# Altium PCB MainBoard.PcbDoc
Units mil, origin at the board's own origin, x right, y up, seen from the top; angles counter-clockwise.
Board outline 3600 x 2800 mil, 2 copper layers (Top Layer, Bottom Layer); 55 components, 52 nets, 242 pads, 74 vias.
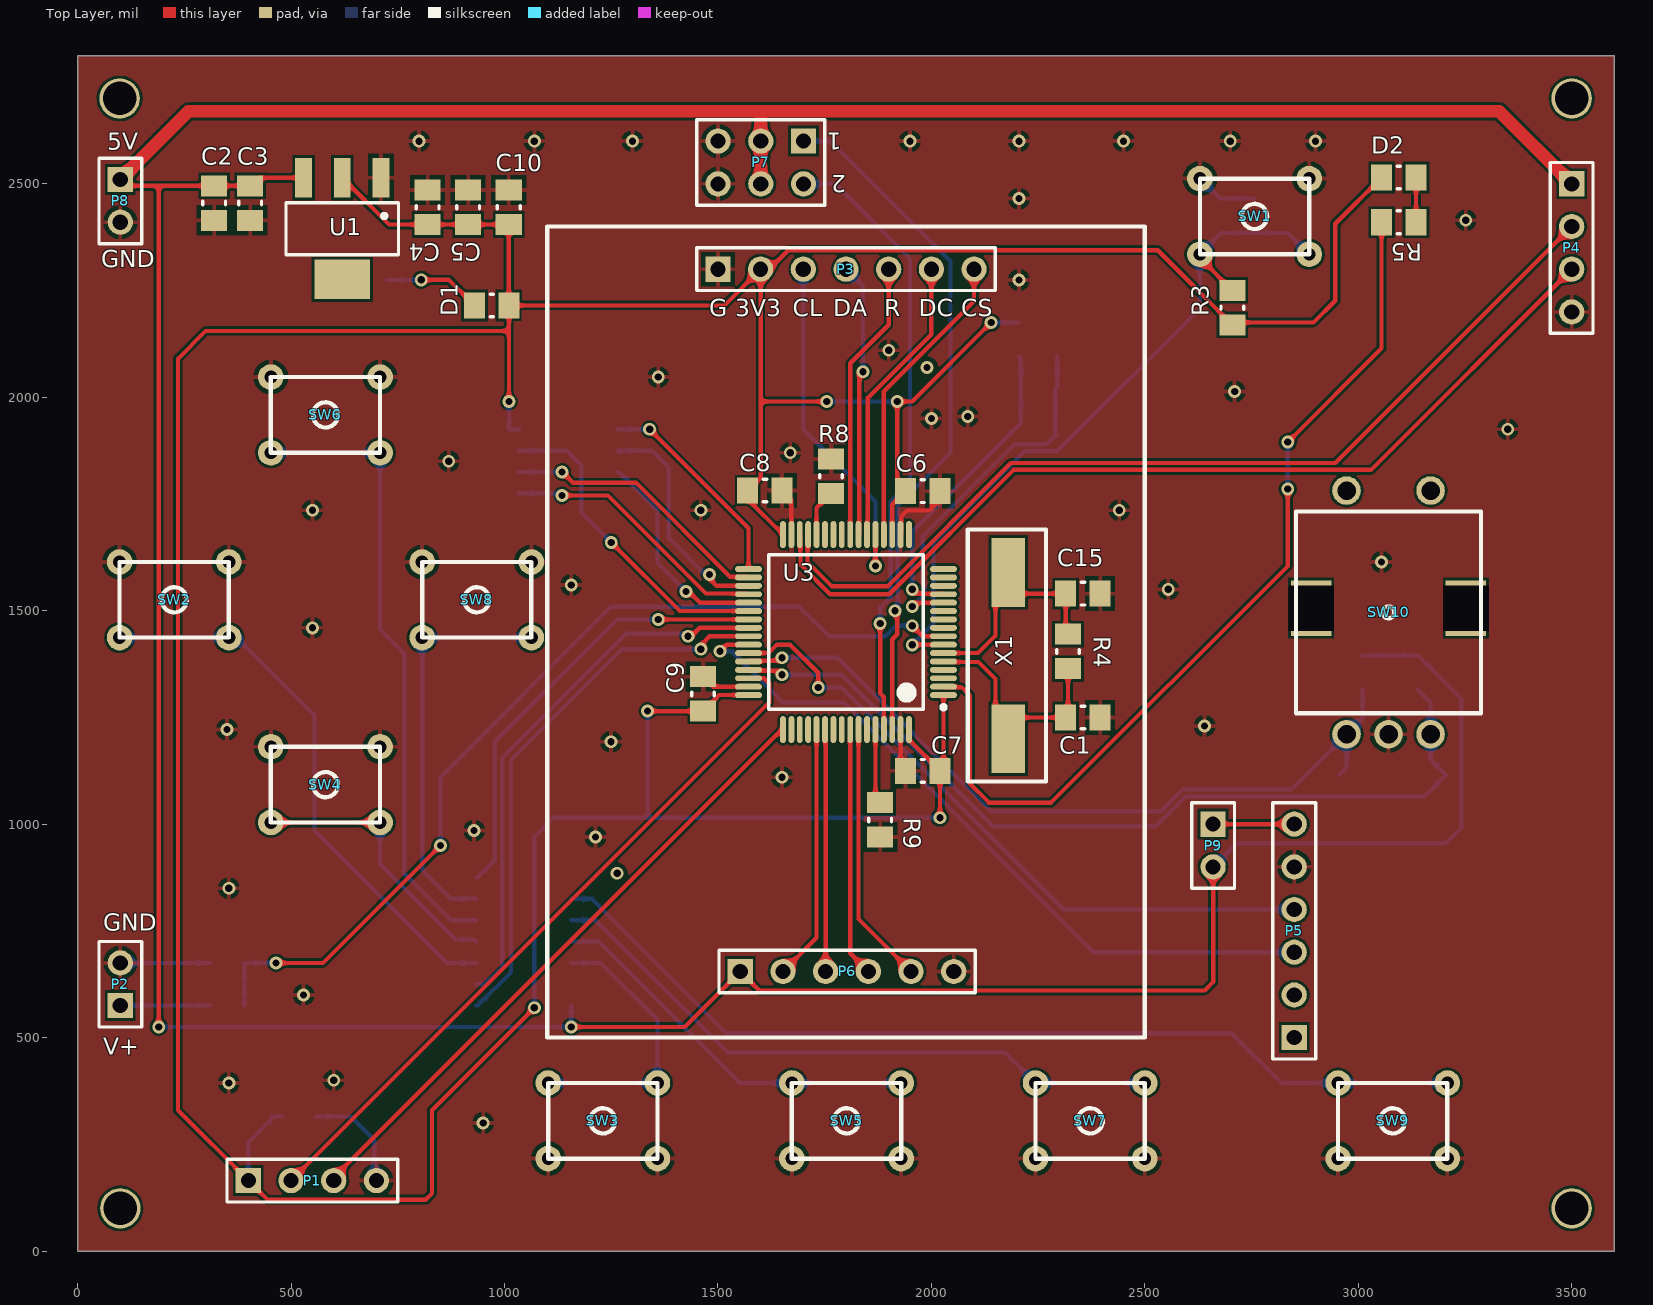
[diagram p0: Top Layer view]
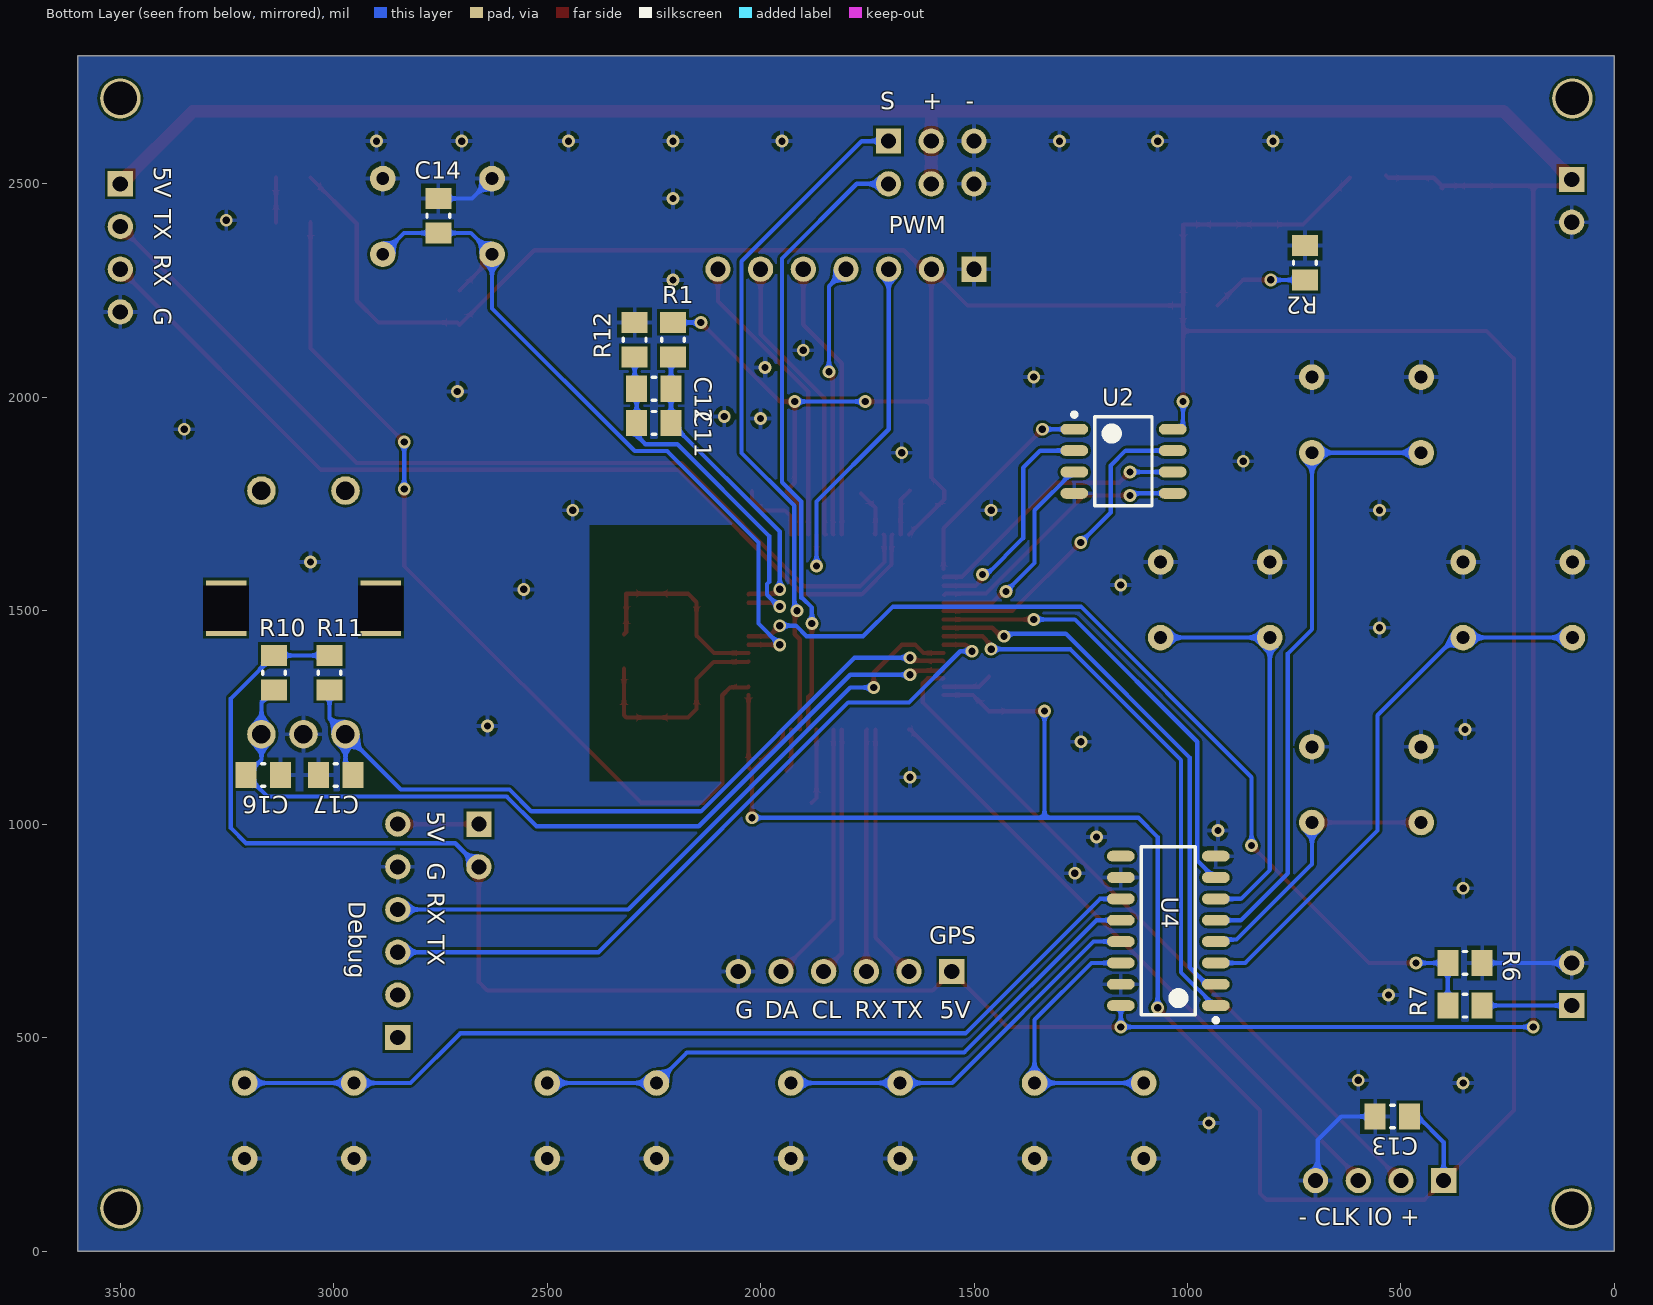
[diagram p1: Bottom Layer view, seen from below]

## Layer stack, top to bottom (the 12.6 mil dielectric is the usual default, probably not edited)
Top Solder: solder mask 0.4, Solder Resist, Dk 3.5
Top Layer: signal copper 1.4
Dielectric 1: dielectric 12.6, FR-4, Dk 4.8
Bottom Layer: signal copper 1.4
Bottom Solder: solder mask 0.4, Solder Resist, Dk 3.5

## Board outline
0,0 0,2800 3600,2800 3600,0

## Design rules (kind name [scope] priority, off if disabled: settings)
Clearance [All] p1: gap=6 ignorepadtopadclearanceinfootprint=TRUE except(0: Arc-Hole Track-Hole SMDPad-Hole THPad-Hole Via-Hole Fill-Hole Poly-Hole Region-Hole Text-Hole; 10: Arc-THPad Arc-Via Arc-Text Track-THPad Track-Via Track-Text SMDPad-THPad SMDPad-Via SMDPad-Text THPad-THPad THPad-Via THPad-Text Via-Via Via-Text Fill-Text Poly-Text Region-Text Text-Text)
PolygonConnect [All] p1: connectstyle=Relief reliefconductorwidth=10 reliefentries=4 polygonreliefangle="90 Angle" airgapwidth=10
RoutingVias [All] p1: holewidth=17 width=30 viastyle="Through Hole" minholewidth=17 minwidth=30 maxholewidth=28 maxwidth=50
SolderMaskExpansion [All] p1: expansion=4
Width [All] p1: maxlimit=30 minlimit=10 preferedwidth=10 minimp=50.000000 maximp=50.000000 favimp=50.000000
30 further rules are at their usual default settings.

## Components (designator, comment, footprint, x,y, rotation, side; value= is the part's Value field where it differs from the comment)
C1 "22p" 0805 2355,1250 r0 top
C2 "106" 0805 320,2455 r90 top
C3 "104" 0805 404.33,2455 r90 top
C4 "104" 0805 820,2445 r270 top
C5 "106" 0805 915,2445 r270 top
C6 "104" 0805 1980,1780 r180 top
C7 "104" 0805 1980,1125 r0 top
C8 "104" 0805 1610,1781.5 r180 top
C9 "104" 0805 1465,1305 r270 top
C10 "104" 0805 1010,2445 r270 top
C11 "104" 0805 2250,1940 r180 bottom
C12 "106" 0805 2250,2020 r180 bottom
C13 "104" 0805 520,315 r180 bottom
C14 "105" 0805 2755,2425 r270 bottom
C15 "22p" 0805 2355,1540 r0 top
C16 "104" 0805 3165,1115 r0 bottom
C17 "104" 0805 2995,1115 r0 bottom
D1 "LED" 0805 970,2215 r180 top
D2 "LED" 0805 3095,2515 r0 top
P1 "SWD" HDR1X4 400,165 r0 top
P2 "BAT Power" HDR1X2 100,575 r90 top
P3 "OLED" HDR1X7 1500,2300 r0 top
P4 "Telem" HDR1X4 3500,2500 r270 top
P5 "Debug" HDR1X6 2850,500 r90 top
P6 "GPS" HDR1X6 1552.36,655 r0 top
P7 "PWM" HDR2X3 1700.35,2600 r180 top
P8 "GND" HDR1X2 100,2510 r270 top
P9 "Header 2" HDR1X2 2660,1000 r270 top
R1 "0R" 0805 2205.35,2135 r90 bottom
R2 "510" 0805 725,2315 r90 bottom
R3 "10k" 0805 2705,2210 r90 top
R4 "1M" 0805 2320,1404.65 r270 top
R5 "510" 0805 3095,2410 r180 top
R6 "5k1" 0805 350,575 r180 bottom
R7 "1k" 0805 350,675 r0 bottom
R8 "10k" 0805 1765,1815 r270 top
R9 "10k" 0805 1880,1010 r270 top
R10 "10k" 0805 3140,1355 r90 bottom
R11 "10k" 0805 3010,1355 r270 bottom
R12 "0R" 0805 2295,2135 r90 bottom
SW1 "" Btn 2885,2335 r180 top
SW2 "" Btn 98.43,1614.17 r0 top
SW3 "" Btn 1102.36,393.7 r0 top
SW4 "" Btn 452.76,1181.1 r0 top
SW5 "" Btn 1673.23,393.7 r0 top
SW6 "" Btn 452.76,2047.24 r0 top
SW7 "" Btn 2244.09,393.7 r0 top
SW8 "" Btn 807.09,1614.17 r0 top
SW9 "" Btn 2952.76,393.7 r0 top
SW10 "EC11" EC11 2972.44,1781.5 r0 top
U1 "AMS1117-3.3" SOT223 620,2395 r270 top
U2 "MB85RS16" SOP8 1150,1850 r180 bottom
U3 "STM32F103R" LQFP64 1800,1450 r180 top
U4 "74LS165" SOP16 1045,750 r0 bottom
X1 "8M" 49SMD 2180,1395 r270 top

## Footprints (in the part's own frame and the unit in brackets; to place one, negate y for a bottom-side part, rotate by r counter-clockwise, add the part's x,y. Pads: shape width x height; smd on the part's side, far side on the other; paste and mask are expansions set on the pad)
49SMD [mm] "Chip Capacitor, 2-Leads, Body 12.65x4.50mm, IPC High Density"
  rect 4.1x2 smd: 1(-4.95,0) 2(4.95,0)
  silkscreen extent -7.5,-2.4 7.5,2.25
0805 [mm]
  rect 1.25x1.55 smd: 1(-1.025,0) 2(1.025,0)
  silkscreen extent -0.1,-0.67 0.1,0.67
Btn [mil]
  round 60 hole 30: 1(0,0) 1(255.91,0) 2(0,-177.17) 2(255.91,-177.17)
  silkscreen extent 0,-177 256,0
EC11 [mm]
  round 1.7 hole 1.1: 1(5,0) 2(0,0) 3(0,-14.5) 4(2.5,-14.5) 5(5,-14.5)
  rect 2.4x3.3 hole 2.7 square: ""(-2.1,-7) ""(7.1,-7)
  silkscreen extent -3,-13.25 8,-1.25
HDR1X2 [mm] "Connector; Header; 2 Position"
  rect 1.5x1.5 hole 0.9: 1(0,0)
  round 1.5 hole 0.9: 2(2.54,0)
  silkscreen extent -1.27,-1.27 3.81,1.27
HDR1X4 [mm] "Connector; Header; 4 Position"
  rect 1.5x1.5 hole 0.9: 1(0,0)
  round 1.5 hole 0.9: 2(2.54,0) 3(5.08,0) 4(7.62,0)
  silkscreen extent -1.27,-1.27 8.89,1.27
HDR1X6 [mm] "Connector; Header; 6 Position"
  rect 1.5x1.5 hole 0.9: 1(0,0)
  round 1.5 hole 0.9: 2(2.54,0) 3(5.08,0) 4(7.62,0) 5(10.16,0) 6(12.7,0)
  silkscreen extent -1.27,-1.27 13.97,1.27
HDR1X7 [mm] "Connector; Header; 7 Position"
  rect 1.5x1.5 hole 0.9: 1(0,0)
  round 1.5 hole 0.9: 2(2.54,0) 3(5.08,0) 4(7.62,0) 5(10.16,0) 6(12.7,0) 7(15.24,0)
  silkscreen extent -1.27,-1.27 16.51,1.27
HDR2X3 [mm] "Connector; Header; 3x2 Position"
  rect 1.5x1.5 hole 0.9: 1(0,0)
  round 1.5 hole 0.9: 2(0,2.54) 3(2.54,0) 4(2.54,2.54) 5(5.08,0) 6(5.08,2.54)
  silkscreen extent -1.27,-1.27 6.35,3.81
LQFP64 [mm] "TSQFP, 64-Leads, Body 10.00x10.00mm, Pitch 0.50mm, IPC Low Density"
  oval 1.6x0.35 smd: 1(-5.8,3.75) 2(-5.8,3.25) 3(-5.8,2.75) 4(-5.8,2.25) 5(-5.8,1.75) 6(-5.8,1.25) 7(-5.8,0.75) 8(-5.8,0.25) 9(-5.8,-0.25) 10(-5.8,-0.75) 11(-5.8,-1.25) 12(-5.8,-1.75) 13(-5.8,-2.25) 14(-5.8,-2.75) 15(-5.8,-3.25) 16(-5.8,-3.75) 33(5.8,-3.75) 34(5.8,-3.25) 35(5.8,-2.75) 36(5.8,-2.25) 37(5.8,-1.75) 38(5.8,-1.25) 39(5.8,-0.75) 40(5.8,-0.25) 41(5.8,0.25) 42(5.8,0.75) 43(5.8,1.25) 44(5.8,1.75) 45(5.8,2.25) 46(5.8,2.75) 47(5.8,3.25) 48(5.8,3.75)
  oval 0.35x1.6 smd: 17(-3.75,-5.8) 18(-3.25,-5.8) 19(-2.75,-5.8) 20(-2.25,-5.8) 21(-1.75,-5.8) 22(-1.25,-5.8) 23(-0.75,-5.8) 24(-0.25,-5.8) 25(0.25,-5.8) 26(0.75,-5.8) 27(1.25,-5.8) 28(1.75,-5.8) 29(2.25,-5.8) 30(2.75,-5.8) 31(3.25,-5.8) 32(3.75,-5.8) 49(3.75,5.8) 50(3.25,5.8) 51(2.75,5.8) 52(2.25,5.8) 53(1.75,5.8) 54(1.25,5.8) 55(0.75,5.8) 56(0.25,5.8) 57(-0.25,5.8) 58(-0.75,5.8) 59(-1.25,5.8) 60(-1.75,5.8) 61(-2.25,5.8) 62(-2.75,5.8) 63(-3.25,5.8) 64(-3.75,5.8)
  silkscreen extent -5.93,-4.6 4.6,4.6
SOP8 [mm]
  oval 1.65x0.65 smd: 1(-2.925,1.905) 2(-2.925,0.635) 3(-2.925,-0.635) 4(-2.925,-1.905) 5(2.925,-1.905) 6(2.925,-0.635) 7(2.925,0.635) 8(2.925,1.905)
  silkscreen extent -3.05,-2.65 1.7,2.9
SOP16 [mm] "SOP, 16-Leads, Body 9.90x3.91mm, Pitch 1.27mm, IPC Low Density"
  oval 1.65x0.65 smd: 1(-2.825,4.445) 2(-2.825,3.175) 3(-2.825,1.905) 4(-2.825,0.635) 5(-2.825,-0.635) 6(-2.825,-1.905) 7(-2.825,-3.175) 8(-2.825,-4.445) 9(2.825,-4.445) 10(2.825,-3.175) 11(2.825,-1.905) 12(2.825,-0.635) 13(2.825,0.635) 14(2.825,1.905) 15(2.825,3.175) 16(2.825,4.445)
  silkscreen extent -2.95,-5 1.6,5.44
SOT223 [mm] "SOT223, 4-Leads, Body 6.50x7.00mm (avg), Pitch 2.30mm, IPC Low Density"
  rect 2.35x1 smd: 1(-3.025,2.3) 2(-3.025,0) 3(-3.025,-2.3)
  rect 2.35x3.3 smd: 4(3.025,0)
  silkscreen extent -1.55,-3.35 1.55,3.35

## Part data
C1 C2 C3 C4 C5 C6 C7 C8 C9 C10 C11 C12 C13 C14 C15 C16 C17: library part Cap
P1 P4: library part "Header 4", "Header, 4-Pin"
P2 P8: library part "Header 2", "Header, 2-Pin"
P3: library part "Header 7", "Header, 7-Pin"
P5 P6: library part "Header 6", "Header, 6-Pin"
P7: library part "Header 3X2", "Header, 3-Pin, Dual row"
P9: "Header, 2-Pin"
R1 R2 R3 R4 R5 R6 R7 R8 R9 R10 R11 R12: library part Res
SW1 SW2 SW3 SW4 SW5 SW6 SW7 SW8 SW9: library part Btn
X1: library part XTAL

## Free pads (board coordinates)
  round 94.49 hole 78.74: ""(98.43,2700) ""(100,100) ""(3500,100) ""(3500,2700)

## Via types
v1: diameter 30, hole 17, Top Layer to Bottom Layer, 74 vias

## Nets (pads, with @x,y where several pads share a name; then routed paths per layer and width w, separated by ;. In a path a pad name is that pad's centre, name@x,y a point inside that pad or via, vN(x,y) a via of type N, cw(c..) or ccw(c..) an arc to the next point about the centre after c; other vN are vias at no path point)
3V3: C4.2 C5.2 C6.2 C7.2 C8.2 C9.2 C10.2 C13.2 D1.1 D2.1 P1.1 P3.2 R1.2 R3.1 U1.2 U2.8 U3.1 U3.19 U3.32 U3.48 U3.64 | length 11312.3
  Top Layer w10: U1.2 729.45,2404.65 C4.2 C5.2 C10.2 1010,2215.35 D1.1 ; v1(1010.35,1990) 1010.35,2155 ; v1(1070,570) 830,330 830,135 815.47,120.47 444.53,120.47 P1.1 235,330 235,2090 300,2155 1010.35,2155 ; v1(1335,1265) 1335.35,1264.65 C9.2 1502.72,1302.36 U3.48 ; U3.32 1569.65,1761.06 C8.2 1600,1811.85 1600,1990 ; v1(1755,1990) 1600,1990 ; U3.19@1906.47,1680.14 U3.19 1908.27,1748.62 C6.2 1920,1799.65 v1(1920,1990) 1955,1990 v1(2140,2175) ; U3.64 1947.64,1197.72 C7.2 ; v1(2020,1015) 2020,1124.65 C7.2 ; U3.1 2028.35,1132.99 C7.2 ; D2.1 2946,2406.35 2946,2226 2895,2175 2710.35,2175 R3.1 2530.12,2344.53 1664.91,2344.53 1620.38,2300 P3.2 ; 1010.35,2155 D1.1 ; D1.1 1515,2215 P3.2 ; 1600,1990 P3.2
  Bottom Layer w10: P1.1 400,255 460,315 C13.2 ; v1(1010.35,1990) 1010.35,1925 U2.8 ; v1(1070,570) 1070,970 1115,1015 1335,1015 ; v1(1335,1265) 1335,1015 ; v1(1755,1990) v1(1920,1990) ; v1(2020,1015) 1335,1015 ; v1(2140,2175) 2205,2175 R1.2
5V: C2.2 C3.2 P4.1 P6.1 P7.3 P7.4 P8.1 P9.2 R10.2 R11.1 U1.3 U4.16 | length 10197.1
  Top Layer w10: P8.1 114.65,2495.35 190,2495.35 ; v1(190,525) 190,2495.35 ; C3.2@403.27,2489.29 404.33,2490.35 399.33,2495.35 C2.2 210,2495.35 190,2495.35 ; C3.2 423.07,2514.09 U1.3 U1.3@535,2519.65 ; v1(1156.22,525) 1422.36,525 P6.1 1596.89,610.47 2640.47,610.47 2660,630 P9.2 ; 1600,2670 1600.35,2669.65
  Top Layer w30: P8.1 260,2670 1600,2670 3330,2670 P4.1 ; P7.4 P7.3 1600.35,2669.65
  Bottom Layer w10: v1(190,525) v1(1156.22,525) U4.16 ; P9.2 2715.47,955.47 3205.47,955.47 3240.96,990.96 3240.96,1294.39 R10.2 R11.1
ADC10: R6.1 R7.2 U3.8 | length 2227.2
  Top Layer w10: v1(465,675) 575,675 v1(850,950) ; v1(1955,1465) 1979.84,1440.16 U3.8
  Bottom Layer w10: R6.1 R7.2 v1(465,675) ; v1(850,950) 850,1110 1249.53,1509.53 1689.53,1509.53 1690,1510 1760,1440 1892.43,1440 1917.43,1465 v1(1955,1465)
GND: C1.2 C2.1 C3.1 C4.1 C5.1 C6.1 C7.1 C8.1 C9.1 C10.1 C13.1 C14.1 C15.2 C16.1 C17.2 P1.4 P2.2 P3.1 P4.4 P5.5 P6.6 P7.5 P7.6 P8.2 R2.2 R7.1 R8.1 R9.2 R12.2 SW1.2 SW2.1 SW3.2 SW4.1 SW5.2 SW6.1 SW7.2 SW8.1 SW9.2 SW10.4 U1.1 U2.4 U3.18 U3.31 U3.47 U3.63 U4.8 U4.10 U4.15 | length 1112.2
  Top Layer w10: C9.1 1488.31,1322.05 U3.47 ; C8.1 1672.05,1759.8 U3.31 ; U3.63@1926.16,1219.86 U3.63 1927.95,1136.69 C7.1 ; U3.18 1929.75,1680.14 1929.75,1721.56 1943.19,1735 1995,1735 2020.35,1760.35 C6.1
  Bottom Layer w10: P2.2 R7.1 ; C13.1 640,315 695,260 695,170 P1.4 ; SW1.2@2629.09,2512.17 2675.91,2465.35 C14.1
  other v1: 950,300 354.33,393.7 600,400 529.45,600 354.33,850 1263.9,885 1213.27,970 928.78,985 1650,1110 1249.53,1192.89 350,1221.65 2640,1230 550,1459.84 2555,1550 1156.22,1560.35 3054.65,1614.17 550,1735.23 1460,1735.23 2440,1735.23 869.65,1850 1669.53,1870.08 3350,1925 2000,1950 2085,1955 2710.35,2013.58 1360,2047.24 1990,2070 1900,2110 2205,2274.65 3251.97,2414.65 2205.35,2465.35 800,2600 1070,2600 1300,2600 1950,2600 2205,2600 2450,2600 2700,2600 2900,2600
NetD1_2: D1.2 R2.1 | length 229.6
  Top Layer w10: v1(805,2275) 869.65,2275 D1.2
  Bottom Layer w10: R2.1 804.65,2274.65 v1(805,2275)
NetD2_2: D2.2 R5.1 | length 105
  Top Layer w10: R5.1 D2.2
NetP2_1: P2.1 R6.2 | length 209.6
  Bottom Layer w10: P2.1 R6.2
NetP5_6: P5.6 P9.1 | length 190
  Top Layer w10: P9.1 P5.6
NetR8_2: R8.2 U3.28 | length 112.9
  Top Layer w10: U3.28@1732.9,1680.14 U3.28 1731.1,1740.75 R8.2
NetR9_1: R9.1 U3.60 | length 175.9
  Top Layer w10: U3.60 1868.9,1061.46 R9.1
NetSW2_2: SW2.2 U4.3 | length 1309.2
  Bottom Layer w10: SW2.2@98.43,1437.01 354.33,1437.01 372.99,1437.01 555,1255 555,985 865,675 U4.3
NetSW3_1: SW3.1 U4.14 | length 661.2
  Bottom Layer w10: SW3.1@1102.36,393.7 1358.27,393.7 1358.27,541.73 1225,675 U4.14
NetSW4_2: SW4.2 U4.4 | length 653.7
  Top Layer w10: SW4.2@452.76,1003.94 SW4.2@708.66,1003.94
  Bottom Layer w10: SW4.2@708.66,1003.94 708.66,906.34 885,730 928.78,730 U4.4
NetSW5_1: SW5.1 U4.13 | length 910.1
  Bottom Layer w10: U4.13 1220,725 1551.3,393.7 1673.23,393.7 SW5.1@1929.13,393.7
NetSW6_2: SW6.2 U4.5 | length 1478.7
  Bottom Layer w10: SW6.2@452.76,1870.08 708.66,1870.08 708.66,1456.34 765,1400 765,885 875,775 U4.5
NetSW7_1: SW7.1 U4.12 | length 1501.7
  Bottom Layer w10: U4.12 1213.27,775 1523.27,465 2172.79,465 2244.09,393.7 SW7.1@2500,393.7
NetSW8_2: SW8.2 U4.6 | length 954.8
  Bottom Layer w10: U4.6 875,825 807.09,892.91 807.09,1437.01 SW8.2@1062.99,1437.01
NetSW9_1: SW9.1 U4.11 | length 2231.1
  Bottom Layer w10: U4.11 1205,825 1520,510 2703.7,510 2820,393.7 2952.76,393.7 SW9.1@3208.66,393.7
NRST: C14.2 R3.2 SW1.1 U3.7 | length 1725.4
  Top Layer w10: v1(1955,1420) 1955.47,1420.47 U3.7 ; SW1.1@2629.09,2335 2629.09,2326.26 R3.2
  Bottom Layer w10: v1(1955,1420) 2005,1470 2005,1660 2219,1874 2295.03,1874 2629.09,2208.07 2629.09,2335 2678.74,2384.65 C14.2 2835.35,2384.65 SW1.1@2885,2335
OSCIN: C1.1 R4.2 U3.5 X1.2 | length 498.1
  Top Layer w10: U3.5 2029.45,1380 2110,1380 2150,1340 2150,1270 2170,1250 C1.1 2320,1255.35 R4.2
OSCOUT: C15.1 R4.1 U3.6 X1.1 | length 487.1
  Top Layer w10: U3.6 2109.21,1400.79 2150,1441.58 2150,1520 2170,1540 C15.1 2314.65,1450.35 R4.1
PA8: U3.41 U4.1 | length 1303.3
  Top Layer w10: v1(1460,1410) 1460,1420 1480.16,1440.16 U3.41
  Bottom Layer w10: U4.1 937.12,575 1015,652.88 1015,1150 1275,1410 v1(1460,1410) v1@1460,1420
PA11: C17.1 R11.2 SW10.3 U3.44 | length 1851
  Top Layer w10: U3.44 1573.45,1382.9 1642.9,1382.9 v1(1650,1390)
  Bottom Layer w10: v1(1650,1390) 1780,1390 2140,1030 2537.37,1030 2588.37,1081 2842.81,1081 SW10.3 ; C17.1 2972.44,1132.79 SW10.3 ; R11.2 3010,1248.19 SW10.3
PA12: C16.2 R10.1 SW10.5 U3.45 | length 2061.9
  Top Layer w10: U3.45 1573.45,1359.62 1640.38,1359.62 v1(1650,1350)
  Bottom Layer w10: v1(1650,1350) 1790,1350 2145,995 2525,995 2595,1065 3155.35,1065 C16.2 3169.29,1151.06 SW10.5 3169.29,1285.35 R10.1
PB5: P6.4 U3.57 | length 584.3
  Top Layer w10: U3.57 1809.84,697.52 P6.4
PB6: P6.5 U3.58 | length 617.5
  Top Layer w10: U3.58 1829.53,777.83 P6.5
PC4: P3.5 U3.24 | length 659
  Top Layer w10: U3.24 1809.84,2079.84 1900,2170 P3.5
PC6: U2.3 U3.37 | length 505.6
  Top Layer w10: v1(1425,1545) 1431.47,1545 1457.57,1518.9 U3.37
  Bottom Layer w10: U2.3 1268.49,1825 1358.27,1735.23 1358.27,1611.73 v1(1425,1545)
PC7: U2.7 U3.38 | length 756.9
  Top Layer w10: v1(1250,1660) 1410.79,1499.21 U3.38
  Bottom Layer w10: U2.7 1145,1875 1180,1840 1180,1730 v1(1250,1660)
PC8: U3.39 U4.7 | length 1051
  Top Layer w10: v1(1360,1479.53) U3.39
  Bottom Layer w10: U4.7 937.12,875 977.26,915.14 977.26,1192.89 1263.9,1479.53 v1(1360,1479.53)
PC9: U3.40 U4.2 | length 1276.4
  Top Layer w10: v1(1430,1440) 1437.57,1440 1457.57,1460 1482.43,1460 1482.58,1459.84 U3.40
  Bottom Layer w10: U4.2 955,625 995,665 995,1156 1285,1446 1424,1446 v1(1430,1440)
PC13: R5.2 U3.2 | length 2166.1
  Top Layer w10: U3.2 2030.14,1320.25 2071.56,1320.25 2090,1301.81 2090,1095 2134.65,1050.35 2280.35,1050.35 2835,1605 v1(2835,1785) ; v1(2835,1895) 3054.65,2114.65 R5.2
  Bottom Layer w10: v1(2835,1785) v1(2835,1895)
S1CLK: P3.3 U3.21 | length 838.3
  Top Layer w10: v1(1868.9,1605) U3.21
  Bottom Layer w10: P3.3 1700,1925 1868.9,1756.1 v1(1868.9,1605)
S1CS: P3.7 U3.20 | length 709.2
  Top Layer w10: U3.20 1888.58,2013.58 2100,2225 P3.7
S1MISO: P3.6 U3.22 | length 685.9
  Top Layer w10: U3.22@1847.42,1678.35 U3.22 1851.01,1680.14 1851.01,1998.64 2000,2147.63 P3.6
S1MOSI: P3.4 U3.23 | length 642.6
  Top Layer w10: U3.23 1831.32,1680.14 1831.32,2051.32 v1(1840,2060)
  Bottom Layer w10: P3.4 1840,2260 v1(1840,2060)
S2CLK: U2.6 U3.34 | length 639.1
  Top Layer w10: v1(1135,1825) 1160,1800 1308.19,1800 1528.44,1579.75 1569.86,1579.75 U3.34
  Bottom Layer w10: U2.6 v1(1135,1825)
S2CS: U2.1 U3.33 | length 498.2
  Top Layer w10: v1(1340,1925) 1571.65,1693.35 U3.33
  Bottom Layer w10: U2.1 v1(1340,1925)
S2MISO: U2.2 U3.35 | length 547.2
  Top Layer w10: v1(1480,1585) 1480,1575 1496.73,1558.27 U3.35
  Bottom Layer w10: U2.2@1270.08,1870.08 U2.2 1345,1875 1385,1835 1385,1670 1470,1585 v1(1480,1585)
S2MOSI: U2.5 U3.36 | length 633.8
  Top Layer w10: v1(1135,1770) 1242.57,1770 1472.2,1540.38 1566.41,1540.38 U3.36@1570,1536.79
  Bottom Layer w10: U2.5 1130,1775 v1(1135,1770)
SWCLK: P1.3 U3.49 | length 1494.2
  Top Layer w10: P1.3 600,172.1 1649.55,1221.65 U3.49
SWDIO: P1.2 U3.46 | length 1684.7
  Top Layer w10: P1.2 1620,1285 1620,1330 1608.27,1341.73 U3.46 U3.46@1573.45,1339.94
T4CH3: P7.2 U3.61 | length 1462
  Top Layer w10: v1(1880,1470) 1880,1306.79 1888.58,1298.21 U3.61 U3.61@1886.79,1223.45
  Bottom Layer w10: P7.2 1775,2500 1950,2325 1950,1801.1 1905,1756.1 1905,1530 1902.57,1530 1880,1507.43 v1(1880,1470)
T4CH4: P7.1 U3.62 | length 1618.2
  Top Layer w10: U3.62 1908.27,1433.27 1920,1445 1920,1495 v1(1915,1500)
  Bottom Layer w10: P7.1 1762.97,2600 2044.53,2318.44 2044.53,1869.53 1921,1746 1921,1506 v1(1915,1500)
U1RX: P5.4 U3.43 | length 1563.3
  Top Layer w10: U3.43 1618.36,1400.79 1637.57,1420 1669.53,1420 1735,1354.53 v1(1735,1320)
  Bottom Layer w10: v1(1735,1320) 1790,1320 2310,800 P5.4
U1TX: P5.3 U3.42 | length 1710.1
  Top Layer w10: v1(1505,1405) 1520.47,1420.47 U3.42
  Bottom Layer w10: v1(1505,1405) 1532.36,1405 1652.36,1285 1795,1285 2380,700 P5.3
U3RX: P4.3 U3.30 | length 2221.8
  Top Layer w10: U3.30 1693.53,1676.55 1693.53,1607.89 1762.84,1538.58 1901.16,1538.58 2192.57,1830 3030,1830 P4.3
U3TX: P4.2 U3.29 | length 2227.7
  Top Layer w10: U3.29 1710,1676.93 1710,1614.05 1767.02,1557.02 1896.97,1557.02 2185.95,1846 2946,1846 P4.2
U5RX: P6.3 U3.54 | length 567.3
  Top Layer w10: U3.54 1752.36,1220.08 P6.3
U5TX: P6.2 U3.53 | length 599.3
  Top Layer w10: P6.2 1731.1,733.74 U3.53
VDDA: C11.2 C12.2 R1.1 U3.13 | length 730
  Top Layer w10: v1(1955,1550) 1965,1540 2026.93,1540 U3.13
  Bottom Layer w10: v1(1955,1550) 1955,1685.35 C11.2 C12.2 2209.65,2090.35 R1.1
VSSA: C11.1 C12.1 R12.1 U3.12 | length 852
  Top Layer w10: v1(1955,1510) 1963.9,1518.9 U3.12
  Bottom Layer w10: v1(1955,1510) 1957.43,1510 1985,1537.57 1985,1562.43 1980,1567.43 1980,1675 2195,1890 2270,1890 2290.35,1910.35 C11.1 C12.1 2295,2024.65 R12.1
pads on no net: P5.1 P5.2 SW10. SW10.1 SW10.2 U1.4 U3.3 U3.4 U3.9 U3.10 U3.11 U3.14 U3.15 U3.16 U3.17 U3.25 U3.26 U3.27 U3.50 U3.51 U3.52 U3.55 U3.56 U3.59 U4.9

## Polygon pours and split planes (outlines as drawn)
GND on Bottom Layer "Bottom Layer-GND" (solid, remove dead copper, pour order 12): 0,2805 5,2800 3600,2800 3600,0 0,0
no net on Bottom Layer "Bottom Layer-No Net" (solid, remove dead copper, pour order 10): 0,2805
GND on Top Layer "Top Layer-GND" (solid, remove dead copper, pour order 14): 0,2800 3600,2800 3600,0 0,0

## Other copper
Bottom Layer:
  pour cut-out: 2050,1700 2400,1700 2400,1100 2050,1100

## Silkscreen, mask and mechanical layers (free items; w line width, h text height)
Top Overlay:
  lines w10: 1100,500 1100,2400 2500,2400 2500,500 1100,500
  text "5V" at 70,2580 h40
  text "G" at 1480,2190 h40
  text "3V3" at 1540,2190 h40
  text "CL" at 1675,2190 h40
  text "DA" at 1770,2190 h40
  text "R" at 1890,2190 h40
  text "DC" at 1970,2190 h40
  text "CS" at 2070,2190 h40
  text "GND" at 60,750 h40
  text "V+" at 60,460 h40
Bottom Overlay:
  text "-" at 1520,2675 h40
  text "+" at 1620,2675 h40
  text "S" at 1720,2675 h40
  text "5V" at 3420,2540 h40 r90
  text "TX" at 3420,2440 h40 r90
  text "RX" at 3420,2335 h40 r90
  text "G" at 3420,2210 h40 r90
  text "5V" at 2780,1030 h40 r90
  text "G" at 2780,910 h40 r90
  text "RX" at 2780,840 h40 r90
  text "TX" at 2780,740 h40 r90
  text "5V" at 1580,545 h40
  text "TX" at 1690,545 h40
  text "RX" at 1780,545 h40
  text "CL" at 1880,545 h40
  text "DA" at 1990,545 h40
  text "G" at 2060,545 h40
  text "- CLK IO +" at 740,60 h40
Mechanical 1:
  the board outline again, w10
